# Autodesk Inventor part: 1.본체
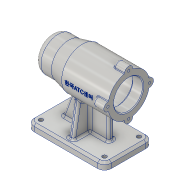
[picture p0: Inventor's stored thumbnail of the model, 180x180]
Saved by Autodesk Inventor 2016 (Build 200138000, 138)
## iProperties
Created: 2019-07
Part Number: 1.본체
Material: 알루미늄 6061
Document SubType Name: Modeling
Designer: 605-03
Density: 2.7 g/cm^3
Appearance: 알루미늄 - 평지
Mass: 644.389 g
Surface Area: 654.091 cm^2
Volume: 238.663 cm^3
Author: 605-03
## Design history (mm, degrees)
sketch "스케치1"
  geometry: L1 (-56, 0)-(56, 0); L2 (56, 21)-(41, 21); L3 (41, 21)-(41, 24); L4 (41, 24)-(-13, 24); L5 (-13, 24)-(-13, 21); L6 (-13, 21)-(-25, 21); L7 (-25, 21)-(-25, 17.5); L8 (-25, 17.5)-(-43, 17.5); L9 (-43, 17.5)-(-43, 16); L10 (-43, 16)-(-47, 16); L11 (-47, 16)-(-47, 10.5); L12 (-47, 10.5)-(-50, 10.5); L13 (-50, 10.5)-(-50, 0); L14 (-50, 0)-(-56, 0); L15 (-56, 0)-(-56, 25); L16 (-56, 25)-(-31, 25); L17 (-31, 25)-(-11, 30); L18 (-11, 30)-(56, 30); L19 (56, 30)-(56, 21); 1 further point
  constraints: 38 end point, 13 perpendicular, 3 point on line, 2 horizontal, 2 midpoint, 2 vertical alignment, 1 collinear, 1 parallel, 1 vertical
  dimensions: "d0" = 112 distance of L1.start L1.end; "d1" = 15 distance of L2.start L2.end; "d2" = 54 distance of L3.end L4.end; "d3" = 12 distance of L5.end L6.end; "d4" = 18 distance of L7.end L8.end; "d5" = 4 distance of L9.end L10.end; "d6" = 3 distance of L11.end L12.end; "d7" = 42 diameter of L2 L1; "d8" = 60 diameter of L18 L1; "d9" = 48 diameter of L4 L1; "d11" = 50 diameter of L16 L1; "d12" = 35 diameter of L8 L1; "d13" = 32 diameter of L10 L1; "d14" = 21 diameter of L12 L1; "d15" = 25 distance of L15.end L16.end; "d16" = 45 distance from line of L17.end L15
revolve "회전1" sketch "스케치1" stored, may be unused: angle "d17" = 90 deg
sketch "스케치2"
  geometry: L1 (-35, -80)-(35, -80); L2 (0, 0)-(0, -80); L3 (-35, -80)-(-35, -70); L4 (-35, -70)-(35, -70); L5 (35, -70)-(35, -80)
  constraints: 10 end point, 2 perpendicular, 2 vertical, 1 horizontal, 1 midpoint, 1 vertical alignment
  dimensions: "d18" = 80 vertical distance of L1.end L2.start; "d19" = 70 distance of L1.start L1.end; "d20" = 10 distance of L1.start L3.end
extrude "돌출1" join sketch "스케치2" distance "d21" = 112; taper "d22" = 0 deg
sketch "스케치3"
  geometry: L1 (-70, 35)-(-70, -35) reference; L2 (-15.435, 18.379)-(-70, 28); L3 (-15.435, -18.379)-(-70, -28); L4 (-70, -35)-(-80, -35) reference; L5 (-80, 35)-(-70, 35) reference; L6 (0, 0)-(-70, 0); A1 r 24 centre (0, 0) between (-15.435, 18.379) and (-15.435, -18.379) reference; 1 further point
  constraints: 6 end point, 2 point on circle, 2 point on line, 1 midpoint
  dimensions: "d23" = 7 distance from line of L3.end L4; "d24" = 7 distance from line of L5 L2.end; "d25" = 100 deg angle of L1 L2; "d26" = 100 deg angle of L1 L3
extrude "돌출2" join sketch "스케치3" stored distance "d27" = 8; taper "d28" = 0 deg
sketch "스케치4"
  geometry: L1 (-31, -25)-(-11, -30) reference; L2 (56, -70)-(-56, -70) reference; L3 (-20.57, -27.607)-(-36, -70); L4 (-56, -70)-(-56, -80) reference; 1 further point
  constraints: 2 end point, 2 point on line
  dimensions: "d29" = 20 distance from line of L3.end L4; "d30" = 110 deg angle of L3 L2
feature "리브1" sketch "스케치4" dims "d31" = 1, "d32" = 8, "d33" = 0, "d34" = 0, "d35" = 1, "d36" = 1
sketch "스케치5"
  geometry: L1 (31, -30)-(31, -70); L2 (56, -70)-(-56, -70) reference; L3 (4, -30)-(56, -30) reference; L4 (56, -80)-(56, -70) reference; 1 further point
  constraints: 2 end point, 2 point on line, 1 vertical
  dimensions: "d37" = 25 distance between parallel lines of L4 L1
feature "리브2" sketch "스케치5" dims "d38" = 1, "d39" = 8, "d40" = 0, "d41" = 0, "d42" = 1, "d43" = 1
sketch "스케치6"
  geometry: C1 r 6 at (0, 30); 3 further points
  constraints: 2 vertical alignment, 1 centre point, 1 coincident, 1 other
  dimensions: "d44" = 6 radius of C1
extrude "돌출3" join sketch "스케치6" distance "d45" = 16; taper "d46" = 0 deg
sketch "스케치7"
  geometry: A1 r 6 centre (0, 0) between (5.97, -0.6) and (-5.97, -0.6) reference; 1 further point
hole "구멍1" sketch "스케치7" at (0, 0) diameter "d47" = 3.242; stored, may be unused: countersink angle "d51" = 90 deg, drill point angle "d53" = 120 deg; dims "d48" = 8, "d49" = 4, "d50" = 2, "d52" = 11
sketch "스케치8"
  geometry: L1 (-10, 10)-(-102, 10); L2 (-102, 10)-(-102, 60); L3 (-102, 60)-(-10, 60); L4 (-10, 60)-(-10, 10); 3 further points
  constraints: 8 end point, 2 midpoint, 2 parallel, 1 horizontal, 1 horizontal alignment, 1 perpendicular, 1 vertical alignment
  dimensions: "d57" = 92 distance of L1.start L1.end; "d58" = 50 distance of L1.end L2.end
hole "구멍2" sketch "스케치8" diameter "d59" = 6; stored, may be unused: countersink angle "d63" = 90 deg, drill point angle "d65" = 120 deg; dims "d60" = 8, "d61" = 4, "d62" = 2, "d64" = 11
hole "구멍3" sketch "스케치8" diameter "d66" = 6; stored, may be unused: countersink angle "d70" = 90 deg, drill point angle "d72" = 120 deg; dims "d67" = 8, "d68" = 4, "d69" = 2, "d71" = 11
fillet "모깎기1" dims "d73" = 10
fillet "모깎기3" dims "d75" = 3
fillet "모깎기4" dims "d76" = 3
fillet "모깎기5" dims "d77" = 3
fillet "모깎기6" dims "d78" = 10
fillet "모깎기7" dims "d79" = 3
fillet "모깎기8" dims "d80" = 3
fillet "모깎기9" dims "d81" = 0.3
chamfer "모따기1" distance "d82" = 1; stored, may be unused: second distance "d83" = 2, angle "d84" = 45 deg
fillet "모깎기10" dims "d85" = 3
fillet "모깎기11" dims "d86" = 1
node "작업 평면1"
sketch "스케치10"
  geometry: L1 (33.5, 5.998)-(33.5, -5.998) reference; L2 (-22.5, 0)-(33.5, 0); 1 further point
  constraints: 2 end point, 1 midpoint, 1 point on line, 1 other
  dimensions: "d87" = 42 distance from line of L1 point (-8.5, 0)
feature "엠보싱1" sketch "스케치10" dims "d17" = 90 deg, "d88" = 0.5, "d89" = 0
chamfer "모따기2" distance "d90" = 3; stored, may be unused: second distance "d91" = 2, angle "d92" = 45 deg
fillet "모깎기12" dims "d93" = 3
node "솔리드1"
pattern_circular "원형 패턴1" dims angle "d55" = 360 deg
